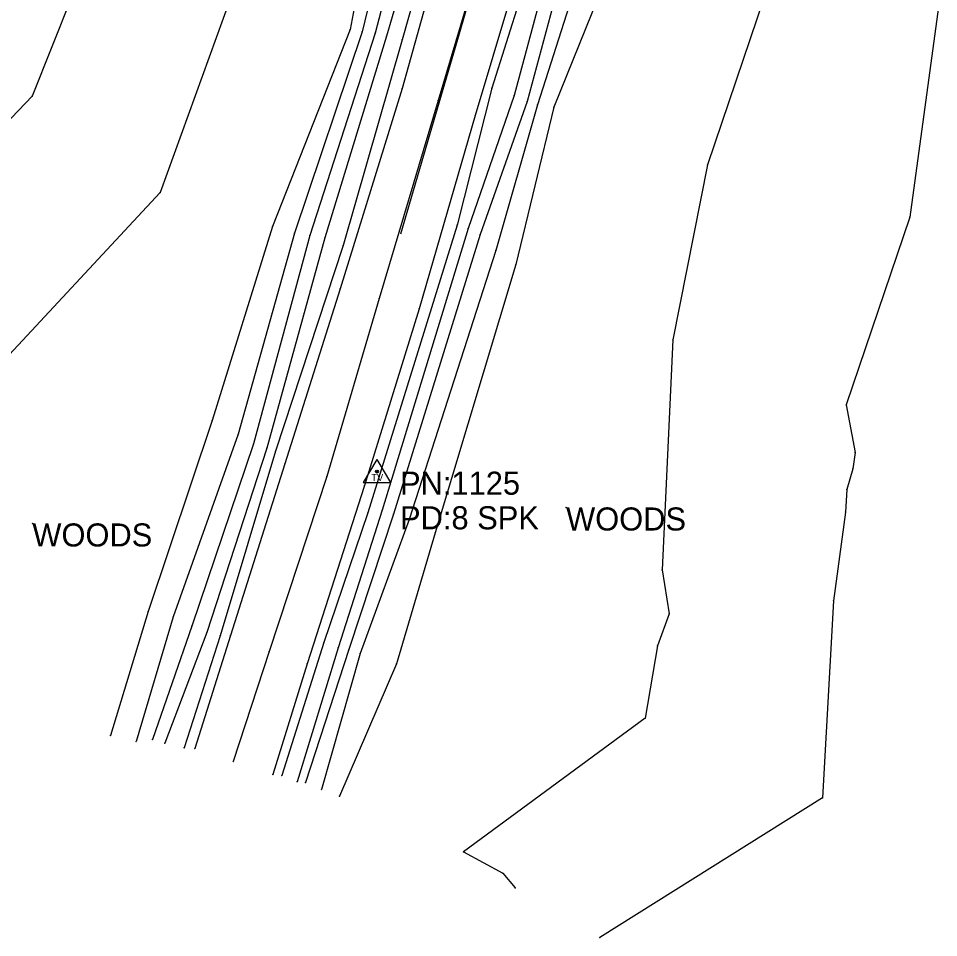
# Model space of a CAD drawing. Extents: x 976456 to 985170, y 1525951 to 1527080.
# Drawn here: x 977697.7 to 977897.2, y 1525975.9 to 1526175.1 of the extents above; entities that cross this region are included whole.
import ezdxf

# ---------------------------------------------------------------- set-up
doc = ezdxf.new("R2010")
doc.units = 0
for name, color, linetype in [('S_BREAKLINE', 7, 'Continuous'), ('S_DITCHLINE', 7, 'Continuous'), ('S_EDGE_PAVEMENT', 7, 'Continuous'), ('S_GRD_PT_SYM', 7, 'Continuous'), ('S_MSC_PT_SYM', 7, 'Continuous'), ('S_PAVEMENT_CROWN', 7, 'Continuous'), ('S_RDW_PT_SYM', 7, 'Continuous'), ('S_SECONDARY_CTL', 7, 'Continuous'), ('S_SECONDARY_CTL_ANNOT', 7, 'Continuous'), ('S_SURVEY_TEXT_ANNOT', 7, 'Continuous')]:
    doc.layers.add(name, color=color, linetype=linetype)

msp = doc.modelspace()

# ---------------------------------------------------------------- linework, layer by layer
at = {"layer": 'S_BREAKLINE'}
for p, q in [((977777.15, 1526213.51), (977769.64, 1526172.7)), ((977789.7, 1526214.07), (977777.52, 1526171.23)), ((977792.98, 1526212.6), (977780.89, 1526170.5)), ((977810.43, 1526191.8), (977800.3, 1526159.99)), ((977814.18, 1526191.86), (977805.18, 1526158.42)), ((977826.79, 1526188.22), (977813.75, 1526155.87)), ((977709.35, 1526180.08), (977700.67, 1526158.25)), ((977743.64, 1526179.35), (977728.46, 1526137.39)), ((977859.86, 1526181.11), (977847.11, 1526143.36)), ((977897.18, 1526177.64), (977890.95, 1526132.04)), ((977769.64, 1526172.7), (977752.8, 1526130)), ((977777.52, 1526171.23), (977764.15, 1526127.54)), ((977780.89, 1526170.5), (977768.07, 1526125.9)), ((977800.3, 1526159.99), (977792.82, 1526130.33)), ((977700.67, 1526158.25), (977661.38, 1526117.16)), ((977805.18, 1526158.42), (977795.19, 1526129.62)), ((977813.75, 1526155.87), (977805.55, 1526121.77)), ((977847.11, 1526143.36), (977839.54, 1526105.44)), ((977728.46, 1526137.39), (977694.73, 1526101.21)), ((977890.95, 1526132.04), (977877.16, 1526091.34)), ((977752.8, 1526130), (977739.67, 1526087.97)), ((977792.82, 1526130.33), (977773.47, 1526067.95)), ((977795.19, 1526129.62), (977776.54, 1526068.52)), ((977764.15, 1526127.54), (977751.52, 1526081.98)), ((977768.07, 1526125.9), (977753.4, 1526081.3)), ((977805.55, 1526121.77), (977788.05, 1526063.62)), ((977839.54, 1526105.44), (977837.25, 1526055.61)), ((977877.16, 1526091.34), (977879.13, 1526081.06)), ((977739.67, 1526087.97), (977725.8, 1526046.58)), ((977751.52, 1526081.98), (977738.55, 1526042.01)), ((977753.4, 1526081.3), (977741.43, 1526041.34)), ((977879.13, 1526081.06), (977878.58, 1526077.53)), ((977878.58, 1526077.53), (977877.27, 1526073.02)), ((977877.27, 1526073.02), (977877.01, 1526068.15)), ((977773.47, 1526067.95), (977763.94, 1526039.86)), ((977776.54, 1526068.52), (977767.03, 1526038.71)), ((977877.01, 1526068.15), (977874.43, 1526048.92)), ((977788.05, 1526063.62), (977779.63, 1526035.24)), ((977837.25, 1526055.61), (977838.75, 1526046.09)), ((977874.43, 1526048.92), (977872.02, 1526006.21)), ((977725.8, 1526046.58), (977717.63, 1526019.71)), ((977838.75, 1526046.09), (977836.22, 1526039.15)), ((977738.55, 1526042.01), (977729.41, 1526018.07)), ((977741.43, 1526041.34), (977733.64, 1526017.08)), ((977763.94, 1526039.86), (977754.77, 1526011.04)), ((977767.03, 1526038.71), (977758.11, 1526009.7)), ((977836.22, 1526039.15), (977833.57, 1526023.46)), ((977779.63, 1526035.24), (977767.3, 1526006.57)), ((977833.57, 1526023.46), (977794.19, 1525994.49)), ((977872.02, 1526006.21), (977823.73, 1525975.98)), ((977794.19, 1525994.49), (977802.69, 1525989.89)), ((977802.69, 1525989.89), (977805.39, 1525986.68))]:
    msp.add_line(p, q, dxfattribs=at)
at = {"layer": 'S_DITCHLINE'}
for p, q in [((977782.13, 1526213.71), (977772.23, 1526172.23)), ((977786.27, 1526214.72), (977775.04, 1526171.91)), ((977817.24, 1526191.51), (977808, 1526157.14)), ((977821.09, 1526190.3), (977810.22, 1526156.39)), ((977772.23, 1526172.23), (977757.52, 1526128.61)), ((977775.04, 1526171.91), (977760.84, 1526128.1)), ((977808, 1526157.14), (977797.77, 1526128.31)), ((977810.22, 1526156.39), (977801.17, 1526124.81)), ((977757.52, 1526128.61), (977745.36, 1526085)), ((977760.84, 1526128.1), (977748.64, 1526082.9)), ((977797.77, 1526128.31), (977779.03, 1526067.71)), ((977801.17, 1526124.81), (977782.39, 1526066.54)), ((977745.36, 1526085), (977731.28, 1526045.42)), ((977748.64, 1526082.9), (977735.27, 1526043.43)), ((977779.03, 1526067.71), (977769.3, 1526038.33)), ((977782.39, 1526066.54), (977771.78, 1526037.49)), ((977731.28, 1526045.42), (977723.21, 1526018.45)), ((977735.27, 1526043.43), (977726.75, 1526018.86)), ((977769.3, 1526038.33), (977759.94, 1526009.54)), ((977771.78, 1526037.49), (977763.39, 1526008.05))]:
    msp.add_line(p, q, dxfattribs=at)
at = {"layer": 'S_EDGE_PAVEMENT'}
for p, q in [((977793.09, 1526203.88), (977780.86, 1526159.93)), ((977810.19, 1526199.14), (977796.72, 1526154.04)), ((977780.86, 1526159.93), (977767.43, 1526116.54)), ((977796.72, 1526154.04), (977784.57, 1526112.21)), ((977767.43, 1526116.54), (977755.48, 1526078.57)), ((977784.57, 1526112.21), (977772.73, 1526073.91)), ((977755.48, 1526078.57), (977743.65, 1526041.38)), ((977772.73, 1526073.91), (977760.32, 1526035.25)), ((977743.65, 1526041.38), (977735.92, 1526016.87)), ((977760.32, 1526035.25), (977752.87, 1526011.27))]:
    msp.add_line(p, q, dxfattribs=at)
at = {"layer": 'S_GRD_PT_SYM'}
for points in [[(977769.64, 1526172.7), (977769.64, 1526172.75), (977769.64, 1526172.7), (977769.59, 1526172.7), (977769.64, 1526172.7), (977769.64, 1526172.65), (977769.64, 1526172.7), (977769.69, 1526172.7)], [(977772.23, 1526172.23), (977772.23, 1526172.28), (977772.23, 1526172.23), (977772.18, 1526172.23), (977772.23, 1526172.23), (977772.23, 1526172.18), (977772.23, 1526172.23), (977772.28, 1526172.23)], [(977775.04, 1526171.91), (977775.04, 1526171.96), (977775.04, 1526171.91), (977774.99, 1526171.91), (977775.04, 1526171.91), (977775.04, 1526171.86), (977775.04, 1526171.91), (977775.09, 1526171.91)], [(977777.52, 1526171.23), (977777.52, 1526171.28), (977777.52, 1526171.23), (977777.47, 1526171.23), (977777.52, 1526171.23), (977777.52, 1526171.18), (977777.52, 1526171.23), (977777.57, 1526171.23)], [(977780.89, 1526170.5), (977780.89, 1526170.55), (977780.89, 1526170.5), (977780.84, 1526170.5), (977780.89, 1526170.5), (977780.89, 1526170.45), (977780.89, 1526170.5), (977780.94, 1526170.5)], [(977800.3, 1526159.99), (977800.3, 1526160.04), (977800.3, 1526159.99), (977800.25, 1526159.99), (977800.3, 1526159.99), (977800.3, 1526159.94), (977800.3, 1526159.99), (977800.35, 1526159.99)], [(977700.67, 1526158.25), (977700.67, 1526158.3), (977700.67, 1526158.25), (977700.62, 1526158.25), (977700.67, 1526158.25), (977700.67, 1526158.2), (977700.67, 1526158.25), (977700.72, 1526158.25)], [(977805.18, 1526158.42), (977805.18, 1526158.47), (977805.18, 1526158.42), (977805.13, 1526158.42), (977805.18, 1526158.42), (977805.18, 1526158.37), (977805.18, 1526158.42), (977805.23, 1526158.42)], [(977808, 1526157.14), (977808, 1526157.19), (977808, 1526157.14), (977807.95, 1526157.14), (977808, 1526157.14), (977808, 1526157.09), (977808, 1526157.14), (977808.05, 1526157.14)], [(977810.22, 1526156.39), (977810.22, 1526156.44), (977810.22, 1526156.39), (977810.17, 1526156.39), (977810.22, 1526156.39), (977810.22, 1526156.34), (977810.22, 1526156.39), (977810.27, 1526156.39)], [(977813.75, 1526155.87), (977813.75, 1526155.92), (977813.75, 1526155.87), (977813.7, 1526155.87), (977813.75, 1526155.87), (977813.75, 1526155.82), (977813.75, 1526155.87), (977813.8, 1526155.87)], [(977847.11, 1526143.36), (977847.11, 1526143.41), (977847.11, 1526143.36), (977847.06, 1526143.36), (977847.11, 1526143.36), (977847.11, 1526143.31), (977847.11, 1526143.36), (977847.16, 1526143.36)], [(977728.46, 1526137.39), (977728.46, 1526137.44), (977728.46, 1526137.39), (977728.41, 1526137.39), (977728.46, 1526137.39), (977728.46, 1526137.34), (977728.46, 1526137.39), (977728.51, 1526137.39)], [(977890.95, 1526132.04), (977890.95, 1526132.09), (977890.95, 1526132.04), (977890.9, 1526132.04), (977890.95, 1526132.04), (977890.95, 1526131.99), (977890.95, 1526132.04), (977891, 1526132.04)], [(977752.8, 1526130), (977752.8, 1526130.05), (977752.8, 1526130), (977752.75, 1526130), (977752.8, 1526130), (977752.8, 1526129.95), (977752.8, 1526130), (977752.85, 1526130)], [(977792.82, 1526130.33), (977792.82, 1526130.38), (977792.82, 1526130.33), (977792.77, 1526130.33), (977792.82, 1526130.33), (977792.82, 1526130.28), (977792.82, 1526130.33), (977792.87, 1526130.33)], [(977795.19, 1526129.62), (977795.19, 1526129.67), (977795.19, 1526129.62), (977795.14, 1526129.62), (977795.19, 1526129.62), (977795.19, 1526129.57), (977795.19, 1526129.62), (977795.24, 1526129.62)], [(977757.52, 1526128.61), (977757.52, 1526128.66), (977757.52, 1526128.61), (977757.47, 1526128.61), (977757.52, 1526128.61), (977757.52, 1526128.56), (977757.52, 1526128.61), (977757.57, 1526128.61)], [(977760.84, 1526128.1), (977760.84, 1526128.15), (977760.84, 1526128.1), (977760.79, 1526128.1), (977760.84, 1526128.1), (977760.84, 1526128.05), (977760.84, 1526128.1), (977760.89, 1526128.1)], [(977764.15, 1526127.54), (977764.15, 1526127.59), (977764.15, 1526127.54), (977764.1, 1526127.54), (977764.15, 1526127.54), (977764.15, 1526127.49), (977764.15, 1526127.54), (977764.2, 1526127.54)], [(977797.77, 1526128.31), (977797.77, 1526128.36), (977797.77, 1526128.31), (977797.72, 1526128.31), (977797.77, 1526128.31), (977797.77, 1526128.26), (977797.77, 1526128.31), (977797.82, 1526128.31)], [(977768.07, 1526125.9), (977768.07, 1526125.95), (977768.07, 1526125.9), (977768.02, 1526125.9), (977768.07, 1526125.9), (977768.07, 1526125.85), (977768.07, 1526125.9), (977768.12, 1526125.9)], [(977801.17, 1526124.81), (977801.17, 1526124.86), (977801.17, 1526124.81), (977801.12, 1526124.81), (977801.17, 1526124.81), (977801.17, 1526124.76), (977801.17, 1526124.81), (977801.22, 1526124.81)], [(977805.55, 1526121.77), (977805.55, 1526121.82), (977805.55, 1526121.77), (977805.5, 1526121.77), (977805.55, 1526121.77), (977805.55, 1526121.72), (977805.55, 1526121.77), (977805.6, 1526121.77)], [(977839.54, 1526105.44), (977839.54, 1526105.49), (977839.54, 1526105.44), (977839.49, 1526105.44), (977839.54, 1526105.44), (977839.54, 1526105.39), (977839.54, 1526105.44), (977839.59, 1526105.44)], [(977877.16, 1526091.34), (977877.16, 1526091.39), (977877.16, 1526091.34), (977877.11, 1526091.34), (977877.16, 1526091.34), (977877.16, 1526091.29), (977877.16, 1526091.34), (977877.21, 1526091.34)], [(977739.67, 1526087.97), (977739.67, 1526088.02), (977739.67, 1526087.97), (977739.62, 1526087.97), (977739.67, 1526087.97), (977739.67, 1526087.92), (977739.67, 1526087.97), (977739.72, 1526087.97)], [(977745.36, 1526085), (977745.36, 1526085.05), (977745.36, 1526085), (977745.31, 1526085), (977745.36, 1526085), (977745.36, 1526084.95), (977745.36, 1526085), (977745.41, 1526085)], [(977748.64, 1526082.9), (977748.64, 1526082.95), (977748.64, 1526082.9), (977748.59, 1526082.9), (977748.64, 1526082.9), (977748.64, 1526082.85), (977748.64, 1526082.9), (977748.69, 1526082.9)], [(977751.52, 1526081.98), (977751.52, 1526082.03), (977751.52, 1526081.98), (977751.47, 1526081.98), (977751.52, 1526081.98), (977751.52, 1526081.93), (977751.52, 1526081.98), (977751.57, 1526081.98)], [(977753.4, 1526081.3), (977753.4, 1526081.35), (977753.4, 1526081.3), (977753.35, 1526081.3), (977753.4, 1526081.3), (977753.4, 1526081.25), (977753.4, 1526081.3), (977753.45, 1526081.3)], [(977879.13, 1526081.06), (977879.13, 1526081.11), (977879.13, 1526081.06), (977879.08, 1526081.06), (977879.13, 1526081.06), (977879.13, 1526081.01), (977879.13, 1526081.06), (977879.18, 1526081.06)], [(977878.58, 1526077.53), (977878.58, 1526077.58), (977878.58, 1526077.53), (977878.53, 1526077.53), (977878.58, 1526077.53), (977878.58, 1526077.48), (977878.58, 1526077.53), (977878.63, 1526077.53)], [(977877.27, 1526073.02), (977877.27, 1526073.07), (977877.27, 1526073.02), (977877.22, 1526073.02), (977877.27, 1526073.02), (977877.27, 1526072.97), (977877.27, 1526073.02), (977877.32, 1526073.02)], [(977773.47, 1526067.95), (977773.47, 1526068), (977773.47, 1526067.95), (977773.42, 1526067.95), (977773.47, 1526067.95), (977773.47, 1526067.9), (977773.47, 1526067.95), (977773.52, 1526067.95)], [(977776.54, 1526068.52), (977776.54, 1526068.57), (977776.54, 1526068.52), (977776.49, 1526068.52), (977776.54, 1526068.52), (977776.54, 1526068.47), (977776.54, 1526068.52), (977776.59, 1526068.52)], [(977779.03, 1526067.71), (977779.03, 1526067.76), (977779.03, 1526067.71), (977778.98, 1526067.71), (977779.03, 1526067.71), (977779.03, 1526067.66), (977779.03, 1526067.71), (977779.08, 1526067.71)], [(977877.01, 1526068.15), (977877.01, 1526068.2), (977877.01, 1526068.15), (977876.96, 1526068.15), (977877.01, 1526068.15), (977877.01, 1526068.1), (977877.01, 1526068.15), (977877.06, 1526068.15)], [(977782.39, 1526066.54), (977782.39, 1526066.59), (977782.39, 1526066.54), (977782.34, 1526066.54), (977782.39, 1526066.54), (977782.39, 1526066.49), (977782.39, 1526066.54), (977782.44, 1526066.54)], [(977788.05, 1526063.62), (977788.05, 1526063.67), (977788.05, 1526063.62), (977788, 1526063.62), (977788.05, 1526063.62), (977788.05, 1526063.57), (977788.05, 1526063.62), (977788.1, 1526063.62)], [(977837.25, 1526055.61), (977837.25, 1526055.66), (977837.25, 1526055.61), (977837.2, 1526055.61), (977837.25, 1526055.61), (977837.25, 1526055.56), (977837.25, 1526055.61), (977837.3, 1526055.61)], [(977874.43, 1526048.92), (977874.43, 1526048.97), (977874.43, 1526048.92), (977874.38, 1526048.92), (977874.43, 1526048.92), (977874.43, 1526048.87), (977874.43, 1526048.92), (977874.48, 1526048.92)], [(977725.8, 1526046.58), (977725.8, 1526046.63), (977725.8, 1526046.58), (977725.75, 1526046.58), (977725.8, 1526046.58), (977725.8, 1526046.53), (977725.8, 1526046.58), (977725.85, 1526046.58)], [(977838.75, 1526046.09), (977838.75, 1526046.14), (977838.75, 1526046.09), (977838.7, 1526046.09), (977838.75, 1526046.09), (977838.75, 1526046.04), (977838.75, 1526046.09), (977838.8, 1526046.09)], [(977731.28, 1526045.42), (977731.28, 1526045.47), (977731.28, 1526045.42), (977731.23, 1526045.42), (977731.28, 1526045.42), (977731.28, 1526045.37), (977731.28, 1526045.42), (977731.33, 1526045.42)], [(977735.27, 1526043.43), (977735.27, 1526043.48), (977735.27, 1526043.43), (977735.22, 1526043.43), (977735.27, 1526043.43), (977735.27, 1526043.38), (977735.27, 1526043.43), (977735.32, 1526043.43)], [(977738.55, 1526042.01), (977738.55, 1526042.06), (977738.55, 1526042.01), (977738.5, 1526042.01), (977738.55, 1526042.01), (977738.55, 1526041.96), (977738.55, 1526042.01), (977738.6, 1526042.01)], [(977741.43, 1526041.34), (977741.43, 1526041.39), (977741.43, 1526041.34), (977741.38, 1526041.34), (977741.43, 1526041.34), (977741.43, 1526041.29), (977741.43, 1526041.34), (977741.48, 1526041.34)], [(977763.94, 1526039.86), (977763.94, 1526039.91), (977763.94, 1526039.86), (977763.89, 1526039.86), (977763.94, 1526039.86), (977763.94, 1526039.81), (977763.94, 1526039.86), (977763.99, 1526039.86)], [(977767.03, 1526038.71), (977767.03, 1526038.76), (977767.03, 1526038.71), (977766.98, 1526038.71), (977767.03, 1526038.71), (977767.03, 1526038.66), (977767.03, 1526038.71), (977767.08, 1526038.71)], [(977769.3, 1526038.33), (977769.3, 1526038.38), (977769.3, 1526038.33), (977769.25, 1526038.33), (977769.3, 1526038.33), (977769.3, 1526038.28), (977769.3, 1526038.33), (977769.35, 1526038.33)], [(977836.22, 1526039.15), (977836.22, 1526039.2), (977836.22, 1526039.15), (977836.17, 1526039.15), (977836.22, 1526039.15), (977836.22, 1526039.1), (977836.22, 1526039.15), (977836.27, 1526039.15)], [(977771.78, 1526037.49), (977771.78, 1526037.54), (977771.78, 1526037.49), (977771.73, 1526037.49), (977771.78, 1526037.49), (977771.78, 1526037.44), (977771.78, 1526037.49), (977771.83, 1526037.49)], [(977779.63, 1526035.24), (977779.63, 1526035.29), (977779.63, 1526035.24), (977779.58, 1526035.24), (977779.63, 1526035.24), (977779.63, 1526035.19), (977779.63, 1526035.24), (977779.68, 1526035.24)], [(977833.57, 1526023.46), (977833.57, 1526023.51), (977833.57, 1526023.46), (977833.52, 1526023.46), (977833.57, 1526023.46), (977833.57, 1526023.41), (977833.57, 1526023.46), (977833.62, 1526023.46)], [(977717.63, 1526019.71), (977717.63, 1526019.76), (977717.63, 1526019.71), (977717.58, 1526019.71), (977717.63, 1526019.71), (977717.63, 1526019.66), (977717.63, 1526019.71), (977717.68, 1526019.71)], [(977723.21, 1526018.45), (977723.21, 1526018.5), (977723.21, 1526018.45), (977723.16, 1526018.45), (977723.21, 1526018.45), (977723.21, 1526018.4), (977723.21, 1526018.45), (977723.26, 1526018.45)], [(977726.75, 1526018.86), (977726.75, 1526018.91), (977726.75, 1526018.86), (977726.7, 1526018.86), (977726.75, 1526018.86), (977726.75, 1526018.81), (977726.75, 1526018.86), (977726.8, 1526018.86)], [(977729.41, 1526018.07), (977729.41, 1526018.12), (977729.41, 1526018.07), (977729.36, 1526018.07), (977729.41, 1526018.07), (977729.41, 1526018.02), (977729.41, 1526018.07), (977729.46, 1526018.07)], [(977733.64, 1526017.08), (977733.64, 1526017.13), (977733.64, 1526017.08), (977733.59, 1526017.08), (977733.64, 1526017.08), (977733.64, 1526017.03), (977733.64, 1526017.08), (977733.69, 1526017.08)], [(977754.77, 1526011.04), (977754.77, 1526011.09), (977754.77, 1526011.04), (977754.72, 1526011.04), (977754.77, 1526011.04), (977754.77, 1526010.99), (977754.77, 1526011.04), (977754.82, 1526011.04)], [(977758.11, 1526009.7), (977758.11, 1526009.75), (977758.11, 1526009.7), (977758.06, 1526009.7), (977758.11, 1526009.7), (977758.11, 1526009.65), (977758.11, 1526009.7), (977758.16, 1526009.7)], [(977759.94, 1526009.54), (977759.94, 1526009.59), (977759.94, 1526009.54), (977759.89, 1526009.54), (977759.94, 1526009.54), (977759.94, 1526009.49), (977759.94, 1526009.54), (977759.99, 1526009.54)], [(977763.39, 1526008.05), (977763.39, 1526008.1), (977763.39, 1526008.05), (977763.34, 1526008.05), (977763.39, 1526008.05), (977763.39, 1526008), (977763.39, 1526008.05), (977763.44, 1526008.05)], [(977767.3, 1526006.57), (977767.3, 1526006.62), (977767.3, 1526006.57), (977767.25, 1526006.57), (977767.3, 1526006.57), (977767.3, 1526006.52), (977767.3, 1526006.57), (977767.35, 1526006.57)], [(977872.02, 1526006.21), (977872.02, 1526006.26), (977872.02, 1526006.21), (977871.97, 1526006.21), (977872.02, 1526006.21), (977872.02, 1526006.16), (977872.02, 1526006.21), (977872.07, 1526006.21)], [(977794.19, 1525994.49), (977794.19, 1525994.54), (977794.19, 1525994.49), (977794.14, 1525994.49), (977794.19, 1525994.49), (977794.19, 1525994.44), (977794.19, 1525994.49), (977794.24, 1525994.49)], [(977802.69, 1525989.89), (977802.69, 1525989.94), (977802.69, 1525989.89), (977802.64, 1525989.89), (977802.69, 1525989.89), (977802.69, 1525989.84), (977802.69, 1525989.89), (977802.74, 1525989.89)], [(977805.39, 1525986.68), (977805.39, 1525986.73), (977805.39, 1525986.68), (977805.34, 1525986.68), (977805.39, 1525986.68), (977805.39, 1525986.63), (977805.39, 1525986.68), (977805.44, 1525986.68)], [(977823.73, 1525975.98), (977823.73, 1525976.03), (977823.73, 1525975.98), (977823.68, 1525975.98), (977823.73, 1525975.98), (977823.73, 1525975.93), (977823.73, 1525975.98), (977823.78, 1525975.98)]]:
    msp.add_lwpolyline(points, dxfattribs=at)
at = {"layer": 'S_MSC_PT_SYM'}
for points in [[(977816.43, 1526069.14), (977816.43, 1526069.19), (977816.43, 1526069.14), (977816.38, 1526069.14), (977816.43, 1526069.14), (977816.43, 1526069.09), (977816.43, 1526069.14), (977816.48, 1526069.14)], [(977700.72, 1526065.68), (977700.72, 1526065.73), (977700.72, 1526065.68), (977700.67, 1526065.68), (977700.72, 1526065.68), (977700.72, 1526065.63), (977700.72, 1526065.68), (977700.78, 1526065.68)]]:
    msp.add_lwpolyline(points, dxfattribs=at)
at = {"layer": 'S_PAVEMENT_CROWN'}
for p, q in [((977801.82, 1526201.55), (977788.73, 1526157.34)), ((977788.73, 1526157.34), (977775.9, 1526114.44)), ((977775.9, 1526114.44), (977764.55, 1526075.86)), ((977764.55, 1526075.86), (977752.05, 1526037.95)), ((977752.05, 1526037.95), (977744.28, 1526014.11))]:
    msp.add_line(p, q, dxfattribs=at)
msp.add_lwpolyline([(977844.21, 1526481.41), (977843.54, 1526464.03), (977842.87, 1526446.65), (977841.9, 1526432.77), (977840.93, 1526418.89), (977839.74, 1526405.83), (977838.55, 1526392.78), (977837.18, 1526378.23), (977835.8, 1526363.67), (977833.69, 1526347.92), (977831.58, 1526332.17), (977829.1, 1526317.87), (977826.61, 1526303.58), (977821.41, 1526279.65), (977816.2, 1526255.72), (977811.81, 1526238.51), (977807.43, 1526221.29), (977803.88, 1526208.91), (977800.34, 1526196.52), (977796.79, 1526184.14), (977793.25, 1526171.75), (977786.88, 1526150.07), (977780.5, 1526128.38)], dxfattribs=at)
at = {"layer": 'S_RDW_PT_SYM'}
for points in [[(977780.86, 1526159.93), (977780.86, 1526159.98), (977780.86, 1526159.93), (977780.81, 1526159.93), (977780.86, 1526159.93), (977780.86, 1526159.88), (977780.86, 1526159.93), (977780.91, 1526159.93)], [(977788.73, 1526157.34), (977788.73, 1526157.39), (977788.73, 1526157.34), (977788.68, 1526157.34), (977788.73, 1526157.34), (977788.73, 1526157.29), (977788.73, 1526157.34), (977788.78, 1526157.34)], [(977796.72, 1526154.04), (977796.72, 1526154.09), (977796.72, 1526154.04), (977796.67, 1526154.04), (977796.72, 1526154.04), (977796.72, 1526153.99), (977796.72, 1526154.04), (977796.77, 1526154.04)], [(977767.43, 1526116.54), (977767.43, 1526116.59), (977767.43, 1526116.54), (977767.38, 1526116.54), (977767.43, 1526116.54), (977767.43, 1526116.49), (977767.43, 1526116.54), (977767.48, 1526116.54)], [(977775.9, 1526114.44), (977775.9, 1526114.49), (977775.9, 1526114.44), (977775.85, 1526114.44), (977775.9, 1526114.44), (977775.9, 1526114.39), (977775.9, 1526114.44), (977775.95, 1526114.44)], [(977784.57, 1526112.21), (977784.57, 1526112.26), (977784.57, 1526112.21), (977784.52, 1526112.21), (977784.57, 1526112.21), (977784.57, 1526112.16), (977784.57, 1526112.21), (977784.62, 1526112.21)], [(977755.48, 1526078.57), (977755.48, 1526078.62), (977755.48, 1526078.57), (977755.43, 1526078.57), (977755.48, 1526078.57), (977755.48, 1526078.52), (977755.48, 1526078.57), (977755.53, 1526078.57)], [(977764.55, 1526075.86), (977764.55, 1526075.91), (977764.55, 1526075.86), (977764.5, 1526075.86), (977764.55, 1526075.86), (977764.55, 1526075.81), (977764.55, 1526075.86), (977764.6, 1526075.86)], [(977772.73, 1526073.91), (977772.73, 1526073.96), (977772.73, 1526073.91), (977772.68, 1526073.91), (977772.73, 1526073.91), (977772.73, 1526073.86), (977772.73, 1526073.91), (977772.78, 1526073.91)], [(977743.65, 1526041.38), (977743.65, 1526041.43), (977743.65, 1526041.38), (977743.6, 1526041.38), (977743.65, 1526041.38), (977743.65, 1526041.33), (977743.65, 1526041.38), (977743.7, 1526041.38)], [(977752.05, 1526037.95), (977752.05, 1526038), (977752.05, 1526037.95), (977752, 1526037.95), (977752.05, 1526037.95), (977752.05, 1526037.9), (977752.05, 1526037.95), (977752.1, 1526037.95)], [(977760.32, 1526035.25), (977760.32, 1526035.3), (977760.32, 1526035.25), (977760.27, 1526035.25), (977760.32, 1526035.25), (977760.32, 1526035.2), (977760.32, 1526035.25), (977760.37, 1526035.25)], [(977735.92, 1526016.87), (977735.92, 1526016.92), (977735.92, 1526016.87), (977735.87, 1526016.87), (977735.92, 1526016.87), (977735.92, 1526016.82), (977735.92, 1526016.87), (977735.97, 1526016.87)], [(977744.28, 1526014.11), (977744.28, 1526014.16), (977744.28, 1526014.11), (977744.23, 1526014.11), (977744.28, 1526014.11), (977744.28, 1526014.06), (977744.28, 1526014.11), (977744.33, 1526014.11)], [(977752.87, 1526011.27), (977752.87, 1526011.32), (977752.87, 1526011.27), (977752.82, 1526011.27), (977752.87, 1526011.27), (977752.87, 1526011.22), (977752.87, 1526011.27), (977752.92, 1526011.27)]]:
    msp.add_lwpolyline(points, dxfattribs=at)
at = {"layer": 'S_SECONDARY_CTL'}
for p, q in [((977775.43, 1526079.51), (977772.42, 1526074.56)), ((977775.43, 1526079.51), (977778.37, 1526074.56)), ((977772.42, 1526074.56), (977778.37, 1526074.56))]:
    msp.add_line(p, q, dxfattribs=at)
for radius in [0.311, 0.183, 0.103]:
    msp.add_circle((977775.43, 1526076.9), radius, dxfattribs=at)

# ---------------------------------------------------------------- texts
msp.add_text('TV', height=1.5, rotation=360, dxfattribs=at).set_placement((977774.22, 1526074.89))
at = {"layer": 'S_SECONDARY_CTL_ANNOT'}
for s, p in [('PN:1125', (977780.43, 1526071.9)), ('PD:8 SPK', (977780.43, 1526064.4))]:
    msp.add_text(s, height=5, dxfattribs=at).set_placement(p)
at = {"layer": 'S_SURVEY_TEXT_ANNOT'}
for s, p in [('WOODS ', (977816.43, 1526064.14)), ('WOODS', (977700.72, 1526060.68))]:
    msp.add_text(s, height=5, dxfattribs=at).set_placement(p)

doc.saveas('drawing.dxf')
